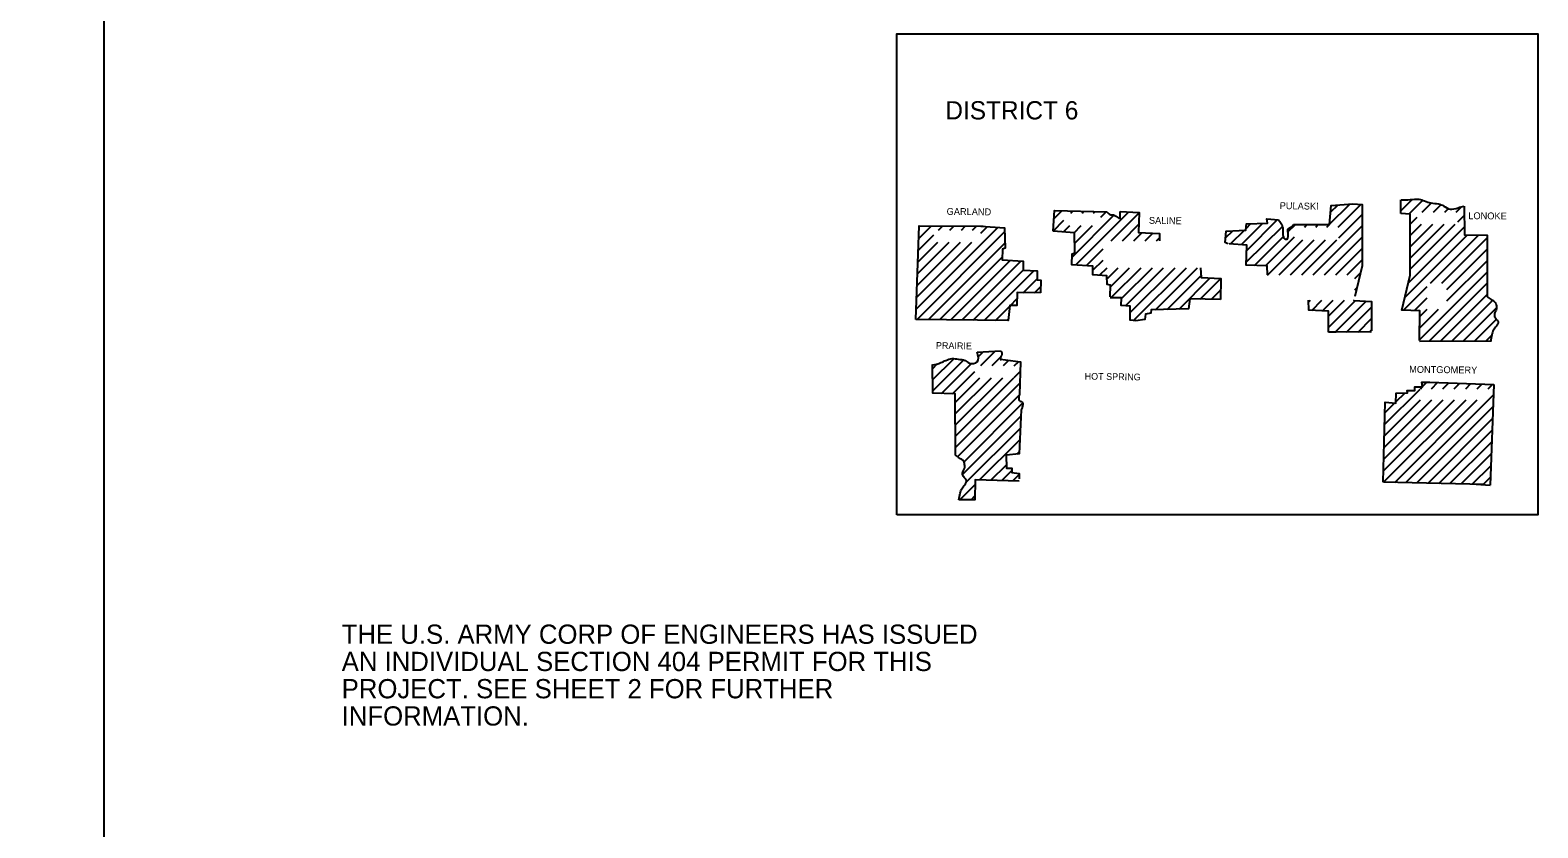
# Model space of a CAD drawing. Extents: x 22866 to 28196, y 1324810 to 1328105.
# Drawn here: x 27047 to 27988, y 1326012 to 1326510 of the extents above; entities that cross this region are included whole.
import ezdxf

# ---------------------------------------------------------------- set-up
doc = ezdxf.new("R2010")
doc.units = 0
doc.layers.add('R_Draft', color=7, linetype='Continuous')
doc.layers.add('R_No Plot', color=7, linetype='Continuous')

msp = doc.modelspace()

# ---------------------------------------------------------------- linework, layer by layer
at = {"layer": 'R_Draft'}
msp.add_line((27727.22, 1326392.26), (27727.22, 1326396.66), dxfattribs=at)
msp.add_lwpolyline([(27587.92, 1326207.46), (27587.92, 1326507.46), (27987.92, 1326507.46), (27987.92, 1326207.46)], close=True, dxfattribs=at)
for points in [[(27902.42, 1326397.06), (27909.52, 1326404.06)], [(27902.42, 1326395.46), (27902.42, 1326403.86)], [(27907.52, 1326395.06), (27916.02, 1326403.56)], [(27685.42, 1326384.46), (27686.32, 1326397.36), (27719.02, 1326396.36)], [(27685.92, 1326392.06), (27691.12, 1326397.26)], [(27696.52, 1326395.56), (27698.02, 1326397.06)], [(27697.42, 1326368.16), (27723.42, 1326394.26)], [(27699.62, 1326363.36), (27732.52, 1326396.26)], [(27703.62, 1326395.56), (27704.72, 1326396.76)], [(27710.72, 1326395.56), (27711.62, 1326396.56)], [(27715.32, 1326393.16), (27718.52, 1326396.36)], [(27721.72, 1326378.36), (27739.02, 1326395.66)], [(27727.22, 1326396.66), (27739.12, 1326395.96), (27738.72, 1326383.46), (27751.82, 1326382.96), (27751.92, 1326378.36)], [(27835.52, 1326388.46), (27858.02, 1326388.56), (27859.02, 1326400.36), (27872.42, 1326401.36)], [(27858.02, 1326388.66), (27870.62, 1326401.26)], [(27858.72, 1326396.36), (27863.02, 1326400.66)], [(27863.42, 1326386.96), (27877.42, 1326400.96)], [(27863.72, 1326380.26), (27878.22, 1326394.76)], [(27872.42, 1326401.36), (27878.22, 1326400.96), (27878.32, 1326362.76), (27873.72, 1326343.66)], [(27914.12, 1326316.26), (27914.22, 1326334.66), (27903.12, 1326335.16), (27908.32, 1326356.86), (27908.22, 1326395.06), (27902.42, 1326395.46)], [(27915.72, 1326396.16), (27921.42, 1326401.86)], [(27922.82, 1326396.16), (27927.42, 1326400.76)], [(27929.92, 1326396.16), (27932.02, 1326398.26)], [(27936.92, 1326396.16), (27940.02, 1326399.26)], [(27937.92, 1326390.16), (27941.92, 1326394.16)], [(27941.92, 1326400.06), (27942.12, 1326382.16), (27956.22, 1326381.86), (27956.32, 1326343.46)], [(27599.72, 1326329.36), (27601.92, 1326387.66), (27641.92, 1326387.46)], [(27600.02, 1326335.76), (27650.92, 1326386.66)], [(27601.62, 1326379.76), (27609.42, 1326387.56)], [(27601.92, 1326387.06), (27602.42, 1326387.66)], [(27614.02, 1326385.06), (27616.52, 1326387.56)], [(27621.12, 1326385.06), (27623.52, 1326387.46)], [(27628.22, 1326385.06), (27630.62, 1326387.46)], [(27635.22, 1326385.06), (27637.62, 1326387.46)], [(27640.32, 1326387.46), (27655.22, 1326386.36), (27655.62, 1326373.76), (27653.92, 1326373.16), (27653.72, 1326366.46), (27666.82, 1326365.56), (27666.82, 1326360.06), (27675.52, 1326359.56), (27675.62, 1326354.06), (27677.72, 1326353.76), (27677.62, 1326345.86)], [(27640.42, 1326383.16), (27644.32, 1326387.06)], [(27685.42, 1326384.46), (27692.22, 1326391.26)], [(27721.12, 1326343.36), (27721.22, 1326350.76), (27719.12, 1326351.06), (27719.02, 1326356.56), (27710.32, 1326357.06), (27710.32, 1326362.56), (27697.22, 1326363.46), (27697.42, 1326370.16), (27699.12, 1326370.76), (27698.72, 1326383.36), (27685.42, 1326384.36)], [(27691.92, 1326383.86), (27695.92, 1326387.86)], [(27698.52, 1326383.36), (27703.02, 1326387.86)], [(27699.02, 1326376.86), (27710.02, 1326387.86)], [(27727.22, 1326392.26), (27727.22, 1326392.16)], [(27728.72, 1326378.36), (27738.82, 1326388.46)], [(27794.52, 1326376.36), (27794.52, 1326376.46), (27792.72, 1326377.36), (27793.42, 1326384.36), (27805.72, 1326385.06), (27806.12, 1326388.96), (27819.22, 1326389.46), (27818.92, 1326392.16), (27826.12, 1326391.36)], [(27793.02, 1326380.16), (27797.52, 1326384.66)], [(27796.22, 1326376.36), (27805.02, 1326385.16)], [(27802.92, 1326375.96), (27816.22, 1326389.26)], [(27805.82, 1326385.96), (27808.92, 1326389.06)], [(27806.02, 1326364.96), (27828.52, 1326387.36)], [(27806.32, 1326372.36), (27825.32, 1326391.36)], [(27832.02, 1326383.86), (27836.62, 1326388.46)], [(27842.22, 1326386.96), (27843.72, 1326388.46)], [(27847.72, 1326357.06), (27878.22, 1326387.66)], [(27849.32, 1326386.96), (27850.72, 1326388.46)], [(27856.32, 1326386.96), (27857.82, 1326388.46)], [(27907.32, 1326352.36), (27942.12, 1326387.16)], [(27908.22, 1326388.66), (27912.72, 1326393.16)], [(27908.32, 1326360.56), (27936.42, 1326388.66)], [(27908.32, 1326367.56), (27929.42, 1326388.66)], [(27908.32, 1326374.66), (27922.42, 1326388.66)], [(27908.32, 1326381.66), (27915.32, 1326388.66)], [(27600.32, 1326343.06), (27634.72, 1326377.46)], [(27600.52, 1326350.36), (27627.62, 1326377.46)], [(27600.72, 1326329.36), (27655.22, 1326383.86)], [(27600.82, 1326357.76), (27620.62, 1326377.46)], [(27601.12, 1326365.06), (27613.52, 1326377.46)], [(27601.42, 1326372.46), (27611.02, 1326382.06)], [(27607.72, 1326329.36), (27655.52, 1326377.06)], [(27735.92, 1326378.36), (27740.82, 1326383.36)], [(27742.92, 1326378.36), (27747.72, 1326383.16)], [(27750.02, 1326378.36), (27751.82, 1326380.16)], [(27819.32, 1326357.06), (27819.12, 1326362.66), (27806.02, 1326363.16), (27806.42, 1326375.66), (27795.22, 1326376.36)], [(27811.12, 1326362.96), (27829.22, 1326381.06)], [(27817.92, 1326362.66), (27836.02, 1326380.76)], [(27819.32, 1326356.96), (27819.42, 1326357.06), (27841.32, 1326378.96)], [(27826.42, 1326357.06), (27848.32, 1326378.96)], [(27833.52, 1326357.06), (27855.42, 1326378.96)], [(27840.62, 1326357.06), (27862.52, 1326378.96)], [(27854.72, 1326357.06), (27878.22, 1326380.56)], [(27905.02, 1326343.06), (27944.02, 1326382.06)], [(27920.92, 1326351.86), (27950.92, 1326381.86)], [(27927.92, 1326351.86), (27956.22, 1326380.16)], [(27614.72, 1326329.16), (27653.72, 1326368.16)], [(27621.72, 1326329.06), (27658.72, 1326366.16)], [(27628.62, 1326328.96), (27665.32, 1326365.66)], [(27706.22, 1326362.86), (27716.72, 1326373.36)], [(27710.32, 1326359.96), (27716.72, 1326366.36)], [(27861.82, 1326357.06), (27878.22, 1326373.56)], [(27868.92, 1326357.06), (27878.22, 1326366.46)], [(27931.22, 1326348.06), (27956.22, 1326373.06)], [(27931.22, 1326340.96), (27956.22, 1326365.96)], [(27635.62, 1326328.86), (27666.82, 1326360.06)], [(27642.62, 1326328.86), (27673.42, 1326359.66)], [(27714.42, 1326356.86), (27719.12, 1326361.56)], [(27719.12, 1326354.56), (27726.12, 1326361.56)], [(27721.22, 1326349.56), (27733.22, 1326361.56)], [(27721.52, 1326342.76), (27740.32, 1326361.56)], [(27728.12, 1326342.36), (27747.42, 1326361.56)], [(27730.72, 1326337.86), (27754.42, 1326361.56)], [(27733.52, 1326333.66), (27761.52, 1326361.56)], [(27735.62, 1326328.56), (27768.62, 1326361.56)], [(27749.42, 1326335.36), (27775.62, 1326361.56)], [(27756.72, 1326335.56), (27777.72, 1326356.56)], [(27777.52, 1326361.56), (27777.82, 1326355.36), (27790.02, 1326354.76), (27789.92, 1326341.76)], [(27873.72, 1326354.86), (27877.22, 1326358.36)], [(27914.22, 1326316.86), (27956.22, 1326358.86)], [(27666.82, 1326345.96), (27675.52, 1326354.66)], [(27673.82, 1326345.86), (27677.62, 1326349.66)], [(27764.02, 1326335.76), (27783.22, 1326355.06)], [(27777.22, 1326341.86), (27790.02, 1326354.76)], [(27784.22, 1326341.86), (27789.92, 1326347.56)], [(27873.72, 1326347.76), (27875.02, 1326349.06)], [(27904.22, 1326335.26), (27918.82, 1326349.86)], [(27920.02, 1326315.66), (27956.22, 1326351.86)], [(27677.62, 1326345.86), (27663.02, 1326346.06), (27662.92, 1326338.06), (27658.42, 1326338.06), (27657.32, 1326328.56), (27599.72, 1326329.36)], [(27649.52, 1326328.66), (27658.32, 1326337.46)], [(27658.92, 1326338.06), (27662.92, 1326342.06)], [(27737.12, 1326328.46), (27733.52, 1326328.76), (27733.52, 1326337.56), (27727.92, 1326337.96), (27728.12, 1326342.76), (27721.12, 1326342.86)], [(27789.92, 1326341.76), (27770.82, 1326342.06), (27769.92, 1326335.96), (27746.62, 1326335.26), (27746.42, 1326333.26), (27743.12, 1326332.66), (27742.72, 1326329.26), (27737.12, 1326328.46)], [(27857.22, 1326321.46), (27857.32, 1326334.46), (27845.12, 1326335.06), (27844.82, 1326341.26)], [(27844.92, 1326340.16), (27846.02, 1326341.26)], [(27846.82, 1326334.96), (27853.12, 1326341.26)], [(27853.62, 1326334.66), (27860.22, 1326341.26)], [(27857.22, 1326324.26), (27874.02, 1326340.96)], [(27857.32, 1326331.36), (27867.22, 1326341.26)], [(27861.52, 1326321.36), (27880.82, 1326340.76)], [(27873.22, 1326341.26), (27873.12, 1326341.06), (27884.22, 1326340.56), (27884.12, 1326322.16)], [(27911.02, 1326334.96), (27918.82, 1326342.76)], [(27927.12, 1326315.66), (27956.22, 1326344.76)], [(27934.22, 1326315.66), (27959.62, 1326341.06)], [(27656.52, 1326328.56), (27657.42, 1326329.56)], [(27868.62, 1326321.36), (27884.12, 1326336.96)], [(27875.72, 1326321.46), (27884.12, 1326329.86)], [(27914.22, 1326323.96), (27926.02, 1326335.76)], [(27914.22, 1326331.06), (27918.92, 1326335.76)], [(27941.32, 1326315.66), (27961.92, 1326336.36)], [(27948.42, 1326315.76), (27962.12, 1326329.46)], [(27862.02, 1326321.36), (27857.22, 1326321.46)], [(27884.12, 1326321.56), (27862.02, 1326321.36)], [(27882.82, 1326321.46), (27884.12, 1326322.86)], [(27955.52, 1326315.76), (27959.22, 1326319.46)], [(27638.12, 1326308.96), (27652.62, 1326309.66)], [(27639.12, 1326306.36), (27641.82, 1326309.06)], [(27640.42, 1326300.56), (27649.32, 1326309.46)], [(27958.52, 1326315.76), (27914.12, 1326315.56)], [(27610.12, 1326298.56), (27613.32, 1326301.76)], [(27624.52, 1326244.56), (27624.42, 1326282.96), (27610.32, 1326283.26), (27610.12, 1326301.16)], [(27610.22, 1326291.56), (27623.42, 1326304.76)], [(27610.32, 1326284.66), (27629.52, 1326303.86)], [(27615.92, 1326283.16), (27634.52, 1326301.76)], [(27647.42, 1326300.56), (27653.12, 1326306.26)], [(27652.62, 1326304.46), (27665.12, 1326302.86), (27664.42, 1326282.46)], [(27654.52, 1326300.56), (27657.72, 1326303.76)], [(27661.22, 1326300.26), (27664.02, 1326302.96)], [(27622.72, 1326282.96), (27636.62, 1326296.86)], [(27624.42, 1326277.56), (27639.82, 1326292.96)], [(27624.52, 1326256.46), (27661.02, 1326292.96)], [(27624.52, 1326263.56), (27654.02, 1326292.96)], [(27624.52, 1326270.56), (27646.92, 1326292.96)], [(27661.22, 1326293.16), (27664.92, 1326296.86)], [(27891.5, 1326227.87), (27892.6, 1326277.77), (27899.4, 1326277.17), (27899.5, 1326283.27), (27906.5, 1326283.47), (27906.4, 1326285.07), (27911.1, 1326285.07), (27911.2, 1326287.27), (27916, 1326287.17), (27915.6, 1326290.17), (27920.6, 1326290.27)], [(27920.6, 1326290.27), (27960.4, 1326288.77)], [(27624.52, 1326249.36), (27664.62, 1326289.46)], [(27626.02, 1326243.76), (27664.02, 1326281.86)], [(27892.3, 1326263.77), (27914.4, 1326285.87)], [(27899.5, 1326278.07), (27904.9, 1326283.37)], [(27905.6, 1326227.57), (27960.2, 1326282.17)], [(27906.4, 1326284.97), (27906.6, 1326285.07)], [(27914.6, 1326286.07), (27915.7, 1326287.17)], [(27915.9, 1326287.37), (27918.7, 1326290.17)], [(27921.6, 1326286.07), (27925.6, 1326290.07)], [(27928.7, 1326286.07), (27932.4, 1326289.77)], [(27935.8, 1326286.07), (27939.3, 1326289.57)], [(27942.9, 1326286.07), (27946.1, 1326289.27)], [(27950, 1326286.07), (27952.9, 1326288.97)], [(27957, 1326286.07), (27959.7, 1326288.77)], [(27960.4, 1326288.77), (27958.1, 1326225.97)], [(27629.92, 1326240.56), (27666.32, 1326277.06)], [(27665.52, 1326272.86), (27664.32, 1326245.46), (27656.12, 1326244.56), (27656.32, 1326236.46), (27659.62, 1326236.56), (27659.72, 1326233.76), (27664.22, 1326233.26), (27664.32, 1326229.96)], [(27891.6, 1326227.77), (27891.7, 1326227.87), (27943.1, 1326279.17)], [(27891.7, 1326234.87), (27936, 1326279.17)], [(27891.8, 1326242.07), (27928.9, 1326279.17)], [(27892, 1326249.37), (27921.8, 1326279.17)], [(27892.1, 1326256.57), (27914.7, 1326279.17)], [(27892.4, 1326270.97), (27898.7, 1326277.27)], [(27898.6, 1326227.67), (27950.1, 1326279.17)], [(27912.4, 1326227.37), (27959.9, 1326274.77)], [(27629.02, 1326232.66), (27665.32, 1326268.96)], [(27919.4, 1326227.17), (27959.6, 1326267.47)], [(27631.52, 1326228.06), (27665.02, 1326261.56)], [(27639.62, 1326229.16), (27664.72, 1326254.16)], [(27926.2, 1326226.97), (27959.3, 1326260.07)], [(27933.1, 1326226.87), (27959.1, 1326252.77)], [(27662.82, 1326245.26), (27664.32, 1326246.76)], [(27940.1, 1326226.67), (27958.8, 1326245.47)], [(27646.52, 1326228.96), (27656.32, 1326238.66)], [(27653.42, 1326228.76), (27659.72, 1326235.06)], [(27946.9, 1326226.47), (27958.5, 1326238.07)], [(27664.32, 1326228.46), (27636.92, 1326229.16), (27636.72, 1326216.86), (27626.72, 1326216.86)], [(27627.42, 1326216.96), (27637.02, 1326226.46)], [(27660.32, 1326228.56), (27664.32, 1326232.66)], [(27954.4, 1326226.27), (27891.7, 1326227.87)], [(27949.4, 1326226.37), (27949.4, 1326226.57), (27958.1, 1326225.97)], [(27953.9, 1326226.37), (27958.2, 1326230.77)], [(27634.52, 1326216.96), (27636.72, 1326219.16)]]:
    msp.add_lwpolyline(points, dxfattribs=at)
for points in [[(27902.62, 1326403.86), (27908.22, 1326404.06), (27913.72, 1326404.26), (27917.22, 1326403.26), (27921.22, 1326401.96), (27925.92, 1326401.36), (27929.22, 1326400.06), (27933.12, 1326398.06), (27938.12, 1326398.96), (27941.92, 1326399.96)], [(27719.02, 1326396.36), (27720.22, 1326395.26), (27721.52, 1326394.46), (27723.12, 1326394.56), (27724.62, 1326393.66), (27727.22, 1326392.26)], [(27826.12, 1326391.36), (27827.82, 1326389.16), (27828.82, 1326386.16), (27828.82, 1326382.76), (27829.62, 1326379.96), (27831.22, 1326379.36), (27832.22, 1326381.76), (27832.02, 1326384.16), (27832.02, 1326385.56), (27833.72, 1326386.76), (27835.52, 1326388.46)], [(27956.32, 1326343.46), (27958.82, 1326341.76), (27961.42, 1326339.76), (27962.12, 1326337.06), (27961.92, 1326335.16), (27961.12, 1326333.56), (27960.92, 1326331.06), (27962.12, 1326329.26), (27963.22, 1326327.76), (27962.12, 1326325.06), (27960.22, 1326322.56), (27959.22, 1326319.76), (27958.52, 1326315.56)], [(27652.72, 1326309.66), (27653.52, 1326308.06), (27653.22, 1326306.66), (27652.62, 1326304.46), (27653.12, 1326303.76)], [(27610.12, 1326301.06), (27610.22, 1326301.06), (27615.32, 1326302.36), (27618.62, 1326303.76), (27622.42, 1326304.96), (27626.22, 1326304.46), (27630.52, 1326303.66), (27633.22, 1326302.06), (27638.12, 1326302.76), (27638.12, 1326308.96)], [(27664.42, 1326282.46), (27664.02, 1326280.46), (27664.82, 1326278.36), (27666.22, 1326277.66), (27666.42, 1326275.66), (27665.92, 1326273.66), (27665.52, 1326272.86)], [(27626.72, 1326216.66), (27627.42, 1326220.86), (27628.42, 1326223.66), (27630.32, 1326226.16), (27631.42, 1326228.86), (27630.32, 1326230.36), (27629.12, 1326232.16), (27629.32, 1326234.66), (27630.12, 1326236.26), (27630.32, 1326238.16), (27629.62, 1326240.86), (27627.02, 1326242.86), (27624.52, 1326244.56)]]:
    msp.add_spline(points, degree=3, dxfattribs=at)
at = {"layer": 'R_No Plot'}
msp.add_lwpolyline([(23759.79, 1327541.9), (27093.11, 1327541.9), (27093.11, 1325408.57), (23759.79, 1325408.57)], close=True, dxfattribs=at)

# ---------------------------------------------------------------- texts
at = {"layer": 'R_Draft'}
for s, height, p in [('DISTRICT 6', 11.4, (27618.22, 1326454.06)), ('THE U.S. ARMY CORP OF ENGINEERS HAS ISSUED', 12, (27241.58, 1326126.95)), ('AN INDIVIDUAL SECTION 404 PERMIT FOR THIS', 12, (27241.58, 1326109.95)), ('PROJECT. SEE SHEET 2 FOR FURTHER', 12, (27241.58, 1326092.95)), ('INFORMATION.', 12, (27241.58, 1326075.95))]:
    msp.add_text(s, height=height, dxfattribs=at).set_placement(p)
for s, height, rotation, p in [('GARLAND', 4.301, 359.36576, (27619.02, 1326394.56)), ('PULASKI', 4.301, 359.05305, (27826.82, 1326398.16)), ('LONOKE', 4.301, 359.49742, (27944.52, 1326391.86)), ('SALINE', 4.301, 359.14914, (27745.22, 1326388.96)), ('PRAIRIE', 4.201, 359.21158, (27612.32, 1326310.96)), ('MONTGOMERY', 4.301, 359.29442, (27907.6, 1326296.07)), ('HOT SPRING', 4.201, 359.22157, (27705.12, 1326291.76))]:
    msp.add_text(s, height=height, rotation=rotation, dxfattribs=at).set_placement(p)

doc.saveas('drawing.dxf')
